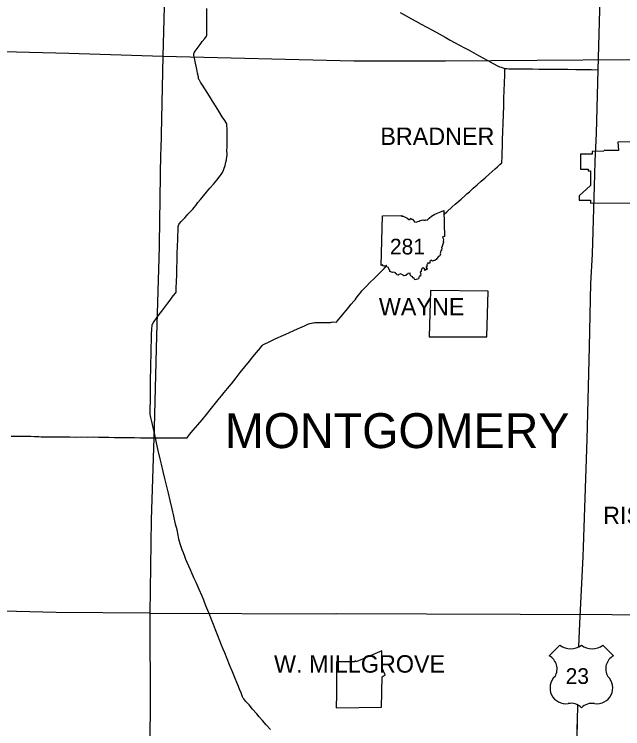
# Model space of a CAD drawing. Extents: x -232 to 448, y 619 to 1059.
# Drawn here: x 165.9 to 201.69, y 774.33 to 816.35 of the extents above; entities that cross this region are included whole.
import ezdxf

# ---------------------------------------------------------------- set-up
doc = ezdxf.new("R2010")
doc.units = 0
doc.layers.add('Default', color=7, linetype='Continuous')

msp = doc.modelspace()

# ---------------------------------------------------------------- linework, layer by layer
at = {"layer": 'Default'}
for p, q in [((199.902, 808.116), (199.209, 808.114)), ((199.209, 808.114), (199.211, 807.247)), ((199.211, 807.247), (199.66, 807.248)), ((199.66, 807.248), (199.661, 807.146)), ((199.661, 807.146), (199.791, 807.147)), ((199.127, 805.677), (199.127, 805.424)), ((199.127, 805.424), (199.799, 805.423)), ((187.476, 801.573), (187.558, 804.502)), ((187.476, 801.573), (187.558, 804.502)), ((197.999, 779.249), (197.365, 778.615)), ((197.999, 779.249), (197.365, 778.615)), ((201.154, 778.615), (200.52, 779.249)), ((201.154, 778.615), (200.52, 779.249))]:
    msp.add_line(p, q, dxfattribs=at)
for points in [[(200.254, 813.093), (200.592, 825.744), (200.852, 836.895)], [(175.068, 829.895), (174.972, 824.878), (174.963, 824.491), (174.796, 819.46), (174.779, 819.001), (174.644, 813.897)], [(177.219, 815.526), (177.218, 815.803), (177.22, 816.134), (177.224, 816.428), (177.228, 816.691)], [(188.6, 816.453), (188.942, 816.267), (189.257, 816.093), (189.515, 815.952), (189.831, 815.778), (190.128, 815.615), (190.496, 815.416), (190.886, 815.202), (191.241, 815.003), (191.548, 814.835), (191.8, 814.698), (192.093, 814.539), (192.379, 814.383), (192.649, 814.233), (192.934, 814.079), (193.204, 813.935), (193.456, 813.794), (193.746, 813.637), (194.069, 813.463), (194.327, 813.322), (194.443, 813.266), (194.539, 813.231), (194.633, 813.206), (194.762, 813.172)], [(178.198, 807.176), (178.226, 807.236), (178.303, 807.45), (178.344, 807.645), (178.378, 807.786), (178.409, 807.96), (178.421, 808.062), (178.411, 808.163), (178.41, 808.305), (178.412, 808.57), (178.411, 808.891), (178.411, 809.197), (178.413, 809.557), (178.408, 809.871), (178.395, 809.915), (178.283, 810.094), (178.134, 810.328), (177.926, 810.657), (177.765, 810.911), (177.563, 811.239), (177.38, 811.533), (177.142, 811.912), (176.937, 812.235), (176.854, 812.361), (176.787, 812.47), (176.762, 812.524), (176.743, 812.576), (176.727, 812.667), (176.675, 812.895), (176.627, 813.124), (176.554, 813.482), (176.492, 813.761), (176.455, 813.931), (176.45, 813.984), (176.46, 814.046), (176.484, 814.086), (176.542, 814.175), (176.661, 814.341), (176.824, 814.565), (176.958, 814.742), (177.102, 814.93), (177.2, 815.058), (177.215, 815.103), (177.219, 815.392), (177.219, 815.526)], [(141.903, 814.75), (149.581, 814.49), (149.638, 814.507), (149.689, 814.52), (149.801, 814.541), (149.887, 814.549), (150.037, 814.53), (150.147, 814.498), (150.227, 814.465), (150.305, 814.456), (150.455, 814.449), (152.851, 814.401), (158.251, 814.316), (163.703, 814.205), (169.114, 814.071), (174.644, 813.897)], [(174.644, 813.897), (174.527, 808.363), (174.498, 808.207), (174.415, 802.839), (174.412, 802.667), (174.27, 797.435), (174.117, 792.054), (173.946, 786.609), (173.874, 781.134)], [(174.644, 813.897), (185.87, 813.619), (191.264, 813.616), (196.652, 813.659), (202.053, 813.7), (207.555, 813.61)], [(194.608, 808.324), (194.611, 808.454), (194.627, 808.962), (194.64, 809.465), (194.657, 809.931), (194.674, 810.453), (194.688, 810.95), (194.704, 811.414), (194.722, 811.852), (194.733, 812.326), (194.749, 812.77), (194.762, 813.172)], [(194.762, 813.172), (194.865, 813.16), (195, 813.149), (195.255, 813.143), (195.592, 813.14), (195.989, 813.137), (196.388, 813.134), (196.764, 813.132), (197.19, 813.128), (197.605, 813.123), (198.034, 813.118), (198.46, 813.114), (198.925, 813.106), (199.379, 813.1), (199.852, 813.098), (200.254, 813.088)], [(200.056, 806.935), (200.08, 807.718), (200.154, 809.348), (200.254, 813.088)], [(199.798, 805.249), (203.173, 805.264), (203.175, 805.446), (204.531, 805.415), (204.658, 808.84)], [(201.4, 808.836), (201.45, 808.345), (200.593, 808.341), (200.583, 808.294), (199.901, 808.288)], [(204.658, 808.84), (201.4, 808.836)], [(192.528, 805.788), (192.673, 805.916), (192.902, 806.127), (193.124, 806.321), (193.367, 806.534), (193.594, 806.734), (193.831, 806.945), (194.005, 807.099), (194.184, 807.255), (194.322, 807.378), (194.469, 807.508), (194.582, 807.623), (194.601, 808.004), (194.608, 808.324)], [(199.901, 808.288), (199.902, 808.116)], [(176.042, 804.51), (176.115, 804.588), (176.293, 804.777), (176.403, 804.895), (176.488, 804.988), (176.573, 805.103), (176.703, 805.272), (176.858, 805.456), (177.035, 805.666), (177.208, 805.88), (177.409, 806.114), (177.616, 806.36), (177.811, 806.604), (178.013, 806.844), (178.073, 806.927), (178.141, 807.051), (178.198, 807.176)], [(199.466, 787.321), (199.604, 791.337), (199.735, 796.785), (199.825, 800.523), (199.914, 802.242), (200.056, 806.935)], [(199.791, 807.147), (199.792, 806.273)], [(199.792, 806.273), (199.127, 805.677)], [(191.84, 805.179), (191.933, 805.263), (192.184, 805.485), (192.428, 805.7), (192.528, 805.788)], [(191.179, 804.594), (191.341, 804.735), (191.658, 805.016), (191.84, 805.179)], [(199.799, 805.423), (199.798, 805.249)], [(187.558, 804.502), (188.695, 804.521), (188.677, 804.486), (188.784, 804.478), (188.898, 804.416), (188.995, 804.376), (189.112, 804.283), (189.183, 804.284), (189.213, 804.36), (189.267, 804.301), (189.331, 804.291), (189.442, 804.151), (189.533, 804.12), (189.643, 804.168), (189.724, 804.176), (189.784, 804.224), (189.94, 804.264), (189.984, 804.24), (190.066, 804.245), (190.108, 804.263), (190.18, 804.247), (190.307, 804.353), (190.437, 804.479), (190.638, 804.598), (190.938, 804.71), (191.175, 804.81), (191.209, 803.29)], [(187.558, 804.502), (188.695, 804.521), (188.677, 804.486), (188.784, 804.478), (188.898, 804.416), (188.995, 804.376), (189.112, 804.283), (189.183, 804.284), (189.213, 804.36), (189.267, 804.301), (189.331, 804.291), (189.442, 804.151), (189.533, 804.12), (189.643, 804.168), (189.724, 804.176), (189.784, 804.224), (189.94, 804.264), (189.984, 804.24), (190.066, 804.245), (190.108, 804.263), (190.18, 804.247), (190.307, 804.353), (190.437, 804.479), (190.638, 804.598), (190.938, 804.71), (191.175, 804.81), (191.209, 803.29)], [(175.523, 803.393), (175.53, 803.561), (175.536, 803.865), (175.548, 803.928), (175.573, 803.996), (175.613, 804.052), (175.713, 804.161), (175.924, 804.385), (176.042, 804.51)], [(175.487, 802.306), (175.497, 802.7), (175.513, 803.133), (175.523, 803.393)], [(191.209, 803.29), (191.174, 803.269), (191.119, 803.279), (191.083, 803.236), (191.128, 803.165), (191.149, 803.09), (191.13, 803.007), (191.149, 802.939), (191.136, 802.882), (191.102, 802.825), (191.09, 802.771), (191.061, 802.713), (191.064, 802.681), (191.036, 802.656), (191.041, 802.561), (191.027, 802.508), (191.032, 802.463), (190.987, 802.451), (190.997, 802.413), (190.969, 802.384), (190.975, 802.334), (190.942, 802.303), (190.974, 802.239), (190.948, 802.219), (190.927, 802.141), (190.87, 802.125), (190.754, 801.984), (190.713, 801.93), (190.668, 801.917), (190.642, 801.861), (190.586, 801.861), (190.501, 801.823), (190.445, 801.889), (190.349, 801.81), (190.337, 801.718), (190.215, 801.721), (190.22, 801.675), (190.193, 801.662), (190.168, 801.615), (190.182, 801.533), (190.125, 801.512), (190.132, 801.465), (190.169, 801.435), (190.185, 801.344), (190.124, 801.363), (190.074, 801.286), (190.023, 801.304), (190.04, 801.369), (189.953, 801.447), (189.871, 801.385), (189.829, 801.284), (189.828, 801.217), (189.767, 801.176), (189.806, 801.081), (189.799, 801.015), (189.8, 800.953), (189.724, 800.955), (189.678, 800.787)], [(191.209, 803.29), (191.174, 803.269), (191.119, 803.279), (191.083, 803.236), (191.128, 803.165), (191.149, 803.09), (191.13, 803.007), (191.149, 802.939), (191.136, 802.882), (191.102, 802.825), (191.09, 802.771), (191.061, 802.713), (191.064, 802.681), (191.036, 802.656), (191.041, 802.561), (191.027, 802.508), (191.032, 802.463), (190.987, 802.451), (190.997, 802.413), (190.969, 802.384), (190.975, 802.334), (190.942, 802.303), (190.974, 802.239), (190.948, 802.219), (190.927, 802.141), (190.87, 802.125), (190.754, 801.984), (190.713, 801.93), (190.668, 801.917), (190.642, 801.861), (190.586, 801.861), (190.501, 801.823), (190.445, 801.889), (190.349, 801.81), (190.337, 801.718), (190.215, 801.721), (190.22, 801.675), (190.193, 801.662), (190.168, 801.615), (190.182, 801.533), (190.125, 801.512), (190.132, 801.465), (190.169, 801.435), (190.185, 801.344), (190.124, 801.363), (190.074, 801.286), (190.023, 801.304), (190.04, 801.369), (189.953, 801.447), (189.871, 801.385), (189.829, 801.284), (189.828, 801.217), (189.767, 801.176), (189.806, 801.081), (189.799, 801.015), (189.8, 800.953), (189.724, 800.955), (189.678, 800.787)], [(175.131, 799.628), (175.265, 799.806), (175.395, 799.977), (175.413, 800.026), (175.422, 800.082), (175.427, 800.265), (175.441, 800.614), (175.454, 801.031), (175.464, 801.424), (175.471, 801.845), (175.486, 802.252), (175.487, 802.306)], [(186.536, 800.273), (186.606, 800.344), (186.843, 800.585), (187.05, 800.79), (187.262, 801.005), (187.466, 801.21), (187.653, 801.401), (187.777, 801.528)], [(189.678, 800.787), (189.545, 800.755), (189.453, 800.736), (189.421, 800.812), (189.355, 800.852), (189.312, 800.929), (189.217, 800.94), (189.195, 801.045), (189.184, 801.131), (189.055, 801.11), (189.02, 801.057), (188.974, 801.043), (188.947, 800.991), (188.885, 800.986), (188.818, 800.961), (188.774, 801.013), (188.664, 801.065), (188.615, 801.092), (188.511, 801.05), (188.489, 801.001), (188.407, 801.023), (188.388, 801.078), (188.338, 801.094), (188.327, 801.152), (188.221, 801.184), (188.139, 801.171), (187.996, 801.218), (187.987, 801.295), (187.938, 801.388), (187.913, 801.453), (187.822, 801.503), (187.804, 801.58), (187.775, 801.578), (187.748, 801.547), (187.648, 801.532), (187.607, 801.564), (187.551, 801.618), (187.476, 801.573)], [(189.678, 800.787), (189.545, 800.755), (189.453, 800.736), (189.421, 800.812), (189.355, 800.852), (189.312, 800.929), (189.217, 800.94), (189.195, 801.045), (189.184, 801.131), (189.055, 801.11), (189.02, 801.057), (188.974, 801.043), (188.947, 800.991), (188.885, 800.986), (188.818, 800.961), (188.774, 801.013), (188.664, 801.065), (188.615, 801.092), (188.511, 801.05), (188.489, 801.001), (188.407, 801.023), (188.388, 801.078), (188.338, 801.094), (188.327, 801.152), (188.221, 801.184), (188.139, 801.171), (187.996, 801.218), (187.987, 801.295), (187.938, 801.388), (187.913, 801.453), (187.822, 801.503), (187.804, 801.58), (187.775, 801.578), (187.748, 801.547), (187.648, 801.532), (187.607, 801.564), (187.551, 801.618), (187.476, 801.573)], [(185.961, 799.585), (185.968, 799.593), (186.137, 799.816), (186.26, 799.973), (186.345, 800.076), (186.448, 800.183), (186.536, 800.273)], [(193.771, 800.071), (190.382, 800.112), (190.295, 797.378)], [(193.696, 797.385), (193.771, 800.071)], [(173.954, 796.84), (173.961, 797.107), (173.978, 797.511), (173.995, 797.846), (174.006, 798.045), (174.018, 798.099), (174.04, 798.149), (174.07, 798.21), (174.128, 798.285), (174.271, 798.479), (174.426, 798.684), (174.582, 798.894), (174.747, 799.116), (174.93, 799.36), (175.118, 799.61), (175.131, 799.628)], [(184.918, 798.327), (184.998, 798.425), (185.123, 798.576), (185.283, 798.768), (185.418, 798.931), (185.587, 799.131), (185.721, 799.297), (185.869, 799.472), (185.961, 799.585)], [(174.207, 791.436), (174.442, 791.441), (174.765, 791.44), (175.14, 791.443), (175.465, 791.445), (175.786, 791.443), (176.064, 791.442), (176.209, 791.629), (176.422, 791.891), (176.694, 792.212), (176.947, 792.502), (177.196, 792.805), (177.42, 793.084), (177.659, 793.38), (177.898, 793.677), (178.088, 793.913), (178.247, 794.109), (178.435, 794.339), (178.666, 794.624), (178.943, 794.965), (179.19, 795.274), (179.467, 795.613), (179.732, 795.94), (179.939, 796.197), (180.148, 796.451), (180.379, 796.738), (180.487, 796.877), (180.516, 796.903), (180.601, 796.949), (180.892, 797.09), (181.289, 797.272), (181.734, 797.47), (182.058, 797.617), (182.38, 797.762), (182.691, 797.903), (182.965, 798.024), (183.09, 798.083)], [(183.09, 798.083), (183.165, 798.118), (183.229, 798.146), (183.279, 798.161), (183.378, 798.188), (183.467, 798.206), (183.508, 798.207), (183.578, 798.216), (183.737, 798.217), (183.949, 798.22), (184.167, 798.217), (184.358, 798.217), (184.463, 798.221), (184.502, 798.228), (184.543, 798.242), (184.583, 798.249), (184.655, 798.252), (184.854, 798.249), (184.918, 798.327)], [(190.295, 797.378), (193.696, 797.385)], [(178.66, 777.859), (178.566, 778.087), (178.43, 778.437), (178.286, 778.785), (178.194, 779.009), (178.097, 779.251), (177.987, 779.507), (177.85, 779.849), (177.734, 780.15), (177.615, 780.45), (177.513, 780.695), (177.397, 781.006), (177.278, 781.288), (177.171, 781.562), (177.04, 781.886), (176.943, 782.134), (176.783, 782.52), (176.594, 782.937), (176.489, 783.165), (176.369, 783.434), (176.264, 783.675), (176.171, 783.889), (176.077, 784.097), (175.994, 784.282), (175.924, 784.463), (175.843, 784.675), (175.774, 784.845), (175.717, 785.028), (175.658, 785.208), (175.587, 785.48), (175.533, 785.72), (175.473, 786.021), (175.386, 786.367), (175.28, 786.824), (175.177, 787.269), (175.064, 787.747), (174.96, 788.192), (174.847, 788.656), (174.752, 789.053), (174.658, 789.461), (174.556, 789.895), (174.48, 790.212), (174.371, 790.686), (174.27, 791.141), (174.207, 791.436), (174.143, 791.712), (174.061, 792.053), (173.987, 792.392), (173.926, 792.635), (173.904, 792.742), (173.898, 792.82), (173.893, 792.94), (173.895, 793.182), (173.902, 793.602), (173.904, 794.067), (173.909, 794.492), (173.915, 794.973), (173.929, 795.429), (173.938, 795.857), (173.948, 796.291), (173.948, 796.595), (173.954, 796.84)], [(165.718, 791.53), (166.105, 791.532), (166.457, 791.535), (166.795, 791.539), (166.869, 791.539), (167.093, 791.523), (167.336, 791.508), (167.488, 791.496), (167.595, 791.495), (167.722, 791.496), (168.056, 791.494), (168.439, 791.492), (168.832, 791.492), (169.163, 791.488), (169.507, 791.487), (169.88, 791.489), (170.225, 791.487), (170.561, 791.488), (170.843, 791.485), (171.135, 791.481), (171.466, 791.475), (171.8, 791.468), (172.145, 791.463), (172.506, 791.46), (172.971, 791.452), (173.32, 791.447), (173.829, 791.442), (174.207, 791.436)], [(199.359, 784.456), (199.387, 785.002), (199.466, 787.321)], [(199.159, 780.511), (199.359, 784.456)], [(173.874, 781.134), (168.354, 781.169), (162.918, 781.3), (157.567, 781.452), (152.156, 781.582), (141.496, 781.792)], [(173.874, 781.134), (173.888, 775.428), (173.817, 769.992), (173.77, 764.516), (173.702, 759.281), (173.625, 753.835), (173.472, 748.559)], [(173.874, 781.134), (184.723, 781.094), (184.844, 781.097), (190.147, 781.088), (195.65, 781.064), (201.044, 781.051), (206.461, 781.028)], [(199.117, 779.156), (199.159, 780.511)], [(199.117, 779.156), (199.159, 780.511)], [(187.51, 778.907), (186.007, 778.266), (185.981, 778.325), (185.91, 778.257), (184.862, 778.26)], [(187.497, 775.606), (187.539, 777.39), (187.724, 777.494), (187.538, 777.893), (187.51, 778.907)], [(184.862, 778.26), (184.855, 776.354), (184.84, 775.563), (184.84, 775.563), (187.497, 775.606)], [(178.681, 777.809), (178.66, 777.859)], [(178.984, 777.055), (178.893, 777.283), (178.734, 777.683), (178.681, 777.809)], [(179.629, 775.815), (179.527, 775.932), (179.392, 776.085), (179.358, 776.129), (179.325, 776.207), (179.236, 776.435), (179.146, 776.657), (179.045, 776.904), (178.984, 777.055)], [(180.166, 775.203), (180.141, 775.233), (179.917, 775.484), (179.707, 775.727), (179.629, 775.815)], [(198.473, 747.866), (199.046, 775.728)], [(180.961, 774.289), (180.723, 774.563), (180.503, 774.816), (180.307, 775.034), (180.166, 775.203)], [(198.697, 758.761), (198.834, 765.449), (199.032, 775.074)]]:
    msp.add_lwpolyline(points, dxfattribs=at)
for centre, radius, start, end in [((198.629, 780.051), 1.019, 231.813, 308.187), ((198.629, 780.051), 1.019, 231.813, 308.187), ((199.89, 780.051), 1.019, 231.813, 308.187), ((199.89, 780.051), 1.019, 231.813, 308.187), ((196.968, 777.85), 0.862, 329.1175, 62.6108), ((196.968, 777.85), 0.862, 329.1175, 62.6108), ((201.551, 777.85), 0.862, 117.3892, 210.8825), ((201.551, 777.85), 0.862, 117.3892, 210.8825), ((198.343, 776.727), 0.93, 133.0046, 278.7282), ((198.343, 776.727), 0.93, 133.0046, 278.7282), ((200.176, 776.727), 0.93, 261.2718, 46.9954), ((200.176, 776.727), 0.93, 261.2718, 46.9954), ((198.655, 774.993), 0.832, 43.4177, 101.8742), ((198.655, 774.993), 0.832, 43.4177, 101.8742), ((199.881, 774.938), 0.883, 79.9613, 134.7468), ((199.881, 774.938), 0.883, 79.9613, 134.7468)]:
    msp.add_arc(centre, radius, start, end, dxfattribs=at)

# ---------------------------------------------------------------- texts
for s, height, p in [('BRADNER', 1.026, (187.432, 808.664)), ('281', 0.9234, (187.995, 802.226)), ('WAYNE', 1.026, (187.344, 798.639)), ('MONTGOMERY', 2.052, (178.284, 790.835)), ('RISING SUN', 1.026, (200.539, 786.362)), ('W. MILLGROVE', 1.026, (181.178, 777.628)), ('23', 0.9234, (198.333, 776.966))]:
    msp.add_text(s, height=height, dxfattribs=at).set_placement(p)

doc.saveas('drawing.dxf')
